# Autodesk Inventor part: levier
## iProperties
Created: 2002-03
Part Number: levier
Material: Par défaut
Document SubType Name: Modélisation
Designer: User
Control State: 0
Master: False
Checked Out: False
Shininess: 40.0
Length Units: 11269
Angle Units: 11279
Time Units: 11290
Mass Units: 11283
Length Display Precision: 3
Angle Display Precision: 2
Density: 0.0
Volumn: 0.0
Area: 0.0
PropertySet Name: Model Information
Author: User
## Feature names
1. Extrusion1
2. Extrusion2
3. Symétrie1 [Mirror]
4. Extrusion3
5. Congé1 [Fillet]
6. Extrusion5
7. Extrusion6
8. Extrusion7
9. Extrusion8
10. Extrusion9
11. Extrusion10
12. Révolution1 [Revolution]
13. Extrusion11
14. Extrusion12
15. Extrusion13
